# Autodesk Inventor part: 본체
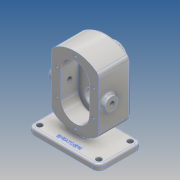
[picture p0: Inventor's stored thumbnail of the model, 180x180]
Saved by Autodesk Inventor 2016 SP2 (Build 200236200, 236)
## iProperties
Created: 2019-03
Part Number: 본체
Material: 알루미늄 6061
Document SubType Name: Modeling
Designer: EZ
Density: 2.7 g/cm^3
Appearance: 알루미늄 - 평지
Mass: 1187.19 g
Surface Area: 719.604 cm^2
Volume: 439.7 cm^3
Author: EZ
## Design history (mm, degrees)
sketch "스케치1"
  geometry: L1 (60, -36.5)-(-60, -36.5); L2 (-60, -36.5)-(-60, 36.5); L3 (-60, 36.5)-(60, 36.5); L4 (60, 36.5)-(60, -36.5); L5 (60, -36.5)-(-60, 36.5); L6 (-60, -36.5)-(60, 36.5); 1 further point
  constraints: 12 end point, 2 midpoint, 2 parallel, 1 horizontal, 1 perpendicular
  dimensions: "d0" = 120 distance of L2.end L3.end; "d1" = 73 distance of L1.end L2.end
extrude "돌출1" new body sketch "스케치1" distance "d2" = 10; taper "d3" = 0 deg
fillet "모깎기1" dims "d4" = 10
sketch "스케치2"
  geometry: L1 (-50, 36.5)-(50, 36.5) reference; L2 (60, 26.5)-(60, -26.5) reference; L3 (50, -36.5)-(-50, -36.5) reference; L4 (-60, -26.5)-(-60, 26.5) reference; A1 r 10 centre (-50, 26.5) between (-50, 36.5) and (-60, 26.5) reference; A2 r 10 centre (50, 26.5) between (60, 26.5) and (50, 36.5) reference; A3 r 10 centre (50, -26.5) between (50, -36.5) and (60, -26.5) reference; A4 r 10 centre (-50, -26.5) between (-60, -26.5) and (-50, -36.5) reference; 5 further points
  constraints: 4 coincident
hole "구멍1" sketch "스케치2" at (-50, 26.5), (-50, -26.5), (50, -26.5), (50, 26.5) diameter "d5" = 9; stored, may be unused: countersink angle "d9" = 90 deg, drill point angle "d11" = 118 deg; dims "d6" = 6, "d7" = 4, "d8" = 2, "d10" = 8
sketch "스케치3"
  geometry: L1 (36.5, 0)-(-36.5, 0) reference; L2 (-36.5, 0)-(-36.5, 10) reference; L3 (-36.5, 10)-(36.5, 10) reference; L4 (36.5, 10)-(36.5, 0) reference; L5 (-16.5, 78)-(36.5, 78); L6 (-16.5, 78)-(-16.5, 138); L7 (-16.5, 138)-(36.5, 138); L8 (36.5, 138)-(36.5, 78)
  constraints: 8 end point, 3 perpendicular, 1 horizontal
  dimensions: "d13" = 78 distance between parallel lines of L5 L1; "d14" = 138 distance between parallel lines of L1 L7; "d15" = 53 distance between parallel lines of L4 L6; "d16" = 53 distance between parallel lines of L6 L8
extrude "돌출2" join sketch "스케치3" stored distance "d18" = 80; taper "d19" = 0 deg
sketch "스케치4"
  geometry: L1 (80, 0)-(80, -120) reference; L2 (0, 0)-(80, 0) reference; L3 (0, 0)-(0, -120) reference; L4 (0, -120)-(80, -120) reference; A1 r 60 centre (40, -60) between (0, -104.721) and (80, -104.721); A2 r 60 centre (40, -60) between (80, -15.279) and (0, -15.279); A3 r 60 centre (40, -60) between (80, -104.721) and (80, -15.279); 2 further points
  constraints: 6 point on circle, 4 point on line, 3 centre point, 2 tangent, 1 midpoint, 1 vertical alignment
  dimensions: "d20" = 120 diameter of A1
extrude "돌출3" cut sketch "스케치4" distance "d21" = 80; taper "d22" = 0 deg
sketch "스케치5"
  geometry: L1 (-50, 36.5)-(50, 36.5) reference; L2 (60, 26.5)-(60, -26.5) reference; L3 (50, -36.5)-(-50, -36.5) reference; L4 (-60, -26.5)-(-60, 26.5) reference; L5 (0, 36.5)-(0, -36.5); L6 (-6, 36.5)-(-6, -6.5); L7 (-6, -6.5)-(6, -6.5); L8 (6, -6.5)-(6, 36.5); C1 r 4.5 at (50, -26.5) reference; C2 r 4.5 at (-50, 26.5) reference; C3 r 4.5 at (-50, -26.5) reference; C4 r 4.5 at (50, 26.5) reference; A1 r 10 centre (-50, 26.5) between (-50, 36.5) and (-60, 26.5) reference; A2 r 10 centre (50, 26.5) between (60, 26.5) and (50, 36.5) reference; A3 r 10 centre (50, -26.5) between (50, -36.5) and (60, -26.5) reference; A4 r 10 centre (-50, -26.5) between (-60, -26.5) and (-50, -36.5) reference
  constraints: 8 end point, 2 midpoint, 2 perpendicular, 2 point on line, 1 vertical
  dimensions: "d27" = 43 distance of L6.start L6.end; "d28" = 6 distance between parallel lines of L5 L6; "d29" = 12 distance between parallel lines of L6 L8
extrude "돌출4" join sketch "스케치5" stored distance "d30" = 80; taper "d31" = 0 deg
sketch "스케치6"
  geometry: L1 (40, 44.721)-(40, -44.721) reference; L2 (-40, 44.721)-(-40, -44.721) reference; L3 (0, 22)-(0, -22); L4 (24, 22)-(24, -22); L5 (-24, -22)-(-24, 22); A1 r 60 centre (0, 0) between (-40, -44.721) and (40, -44.721) reference; A2 r 60 centre (0, 0) between (40, 44.721) and (-40, 44.721) reference; A3 r 24 centre (0, 22) between (24, 22) and (-24, 22); A4 r 24 centre (0, -22) between (-24, -22) and (24, -22); 2 further points
  constraints: 8 end point, 4 point on circle, 4 tangent, 2 centre point, 1 midpoint, 1 parallel, 1 vertical
  dimensions: "d32" = 78 distance of point (0, -78) point (0, 0); "d34" = 22 distance of A1.centre L3.start; "d35" = 44 distance of L3.end L3.start; "d39" = 24 radius of A3
extrude "돌출5" cut sketch "스케치6" distance "d40" = 29; taper "d41" = 0 deg
sketch "스케치7"
  geometry: L1 (24, 22)-(24, -22) reference; L2 (-24, -22)-(-24, 22) reference; L3 (40, 44.721)-(40, -44.721) reference; L4 (-40, 44.721)-(-40, -44.721) reference; L5 (0, 22)-(0, -22); L6 (31, 22)-(31, -22); L7 (-31, -22)-(-31, 22); A1 r 24 centre (0, 22) between (24, 22) and (-24, 22) reference; A2 r 24 centre (0, -22) between (-24, -22) and (24, -22) reference; A3 r 60 centre (0, 0) between (-40, -44.721) and (40, -44.721) reference; A4 r 60 centre (0, 0) between (40, 44.721) and (-40, 44.721) reference; A5 r 31 centre (0, 22) between (31, 22) and (-31, 22); A6 r 31 centre (0, -22) between (-31, -22) and (31, -22); 8 further points
  constraints: 8 end point, 6 point on circle, 4 coincident, 4 tangent, 2 centre point, 1 midpoint, 1 parallel, 1 vertical
  dimensions: "d42" = 31 radius of A5
hole "구멍2" sketch "스케치7" at (0, 53), (-31, 22), (31, 22), (31, -22), (-31, -22), (0, -53) diameter "d43" = 4.134; stored, may be unused: countersink angle "d47" = 90 deg, drill point angle "d49" = 118 deg; dims "d44" = 10, "d45" = 4, "d46" = 2, "d48" = 12
sketch "스케치8"
  geometry: L1 (-33.279, 36.5)-(-33.279, -16.5) reference; L2 (-122.721, -16.5)-(-33.279, -16.5) reference; L3 (-122.721, -16.5)-(-122.721, 36.5) reference; L4 (-122.721, 36.5)-(-33.279, 36.5) reference; L5 (0, -26.5)-(0, 26.5) reference; C1 r 11 at (-78, -2.5); 1 further point
  constraints: 1 centre point
  dimensions: "d51" = 22 diameter of C1; "d52" = 78 distance from line of L5 C1.centre; "d53" = 14 distance from line of L2 C1.centre
extrude "돌출6" join sketch "스케치8" distance "d54" = 8; taper "d55" = 0 deg
hole "구멍3" diameter "d59" = 8.376; stored, may be unused: countersink angle "d63" = 90 deg, drill point angle "d65" = 118 deg; dims "d60" = 20, "d61" = 4, "d62" = 2, "d64" = 27.3, "d103" = 10, "d104" = 10
fillet "모깎기4" dims "d66" = 3
sketch "스케치10"
  geometry: L1 (-40, -44.721)-(-40, 44.721) reference; L2 (40, 44.721)-(40, -44.721) reference; L3 (6, -62.354)-(6, -65) reference; L4 (9, -68)-(60, -68) reference; L5 (60, -68)-(60, -78) reference; L6 (60, -78)-(-60, -78) reference; L7 (-60, -78)-(-60, -68) reference; L8 (-60, -68)-(-9, -68) reference; L9 (-6, -65)-(-6, -62.354) reference; L10 (-24, 22)-(-24, -22) reference; L11 (24, -22)-(24, 22) reference; C1 r 12.5 at (0, -22); A1 r 3 centre (-9, -62.354) between (-6, -62.354) and (-8.571, -59.385) reference; A2 r 60 centre (0, 0) between (-40, -44.721) and (-8.571, -59.385) reference; A3 r 60 centre (0, 0) between (40, 44.721) and (-40, 44.721) reference; A4 r 60 centre (0, 0) between (8.571, -59.385) and (40, -44.721) reference; A5 r 3 centre (9, -62.354) between (8.571, -59.385) and (6, -62.354) reference; A6 r 3 centre (9, -65) between (6, -65) and (9, -68) reference; A7 r 3 centre (-9, -65) between (-9, -68) and (-6, -65) reference; A8 r 24 centre (0, 22) between (24, 22) and (-24, 22) reference; A9 r 24 centre (0, -22) between (-24, -22) and (24, -22) reference; 1 further point
  constraints: 1 centre point, 1 coincident
  dimensions: "d72" = 25 diameter of C1
extrude "돌출7" cut sketch "스케치10" distance "d73" = 15; taper "d74" = 0 deg
sketch "스케치11"
  geometry: L1 (36.5, 122.721)-(36.5, 33.279) reference; L2 (36.5, 119)-(53.5, 119); L3 (53.5, 100)-(36.5, 100); L4 (-16.5, 56)-(-16.5, 100) reference; L5 (-16.5, 78)-(36.5, 78); L6 (-26.5, 0)-(26.5, 0) reference; L7 (53.5, 119)-(53.5, 100); 2 further points
  constraints: 8 end point, 2 horizontal, 2 midpoint, 2 point on line, 1 perpendicular, 1 vertical
  dimensions: "d76" = 78 distance between parallel lines of L6 L5; "d77" = 22 distance between parallel lines of L5 L3; "d79" = 17 distance of L2.start L2.end; "d80" = 38 diameter of L2 L3
revolve "회전1" sketch "스케치11" stored, may be unused: angle "d81" = 90 deg
fillet "모깎기6" dims "d82" = 3
sketch "스케치12"
  geometry: L1 (-16.5, 32)-(12.5, 32) reference; L2 (12.5, 32)-(12.5, 43.5) reference; L3 (12.5, 43.5)-(27.5, 43.5) reference; L4 (27.5, 43.5)-(27.5, 68.5) reference; L5 (27.5, 68.5)-(12.5, 68.5) reference; L6 (12.5, 68.5)-(12.5, 124) reference; L7 (12.5, 124)-(-16.5, 124) reference; L8 (-16.5, 124)-(-16.5, 128.933) reference; L9 (-16.5, 128.933)-(-4.5, 128.933) reference; L10 (-4.5, 128.933)-(-3.258, 131) reference; L11 (-3.258, 131)-(-4.5, 133.067) reference; L12 (-4.5, 133.067)-(-16.5, 133.067) reference; L13 (-16.5, 133.067)-(-16.5, 138) reference; L14 (-16.5, 138)-(36.5, 138) reference; L15 (36.5, 138)-(36.5, 122) reference; L16 (39.5, 119)-(53.5, 119) reference; L17 (53.5, 119)-(53.5, 81) reference; L18 (53.5, 81)-(39.5, 81) reference; L19 (36.5, 78)-(36.5, 0) reference; L20 (36.5, 0)-(-36.5, 0) reference; L21 (-36.5, 0)-(-36.5, 10) reference; L22 (-36.5, 10)-(-6.5, 10) reference; L23 (-6.5, 10)-(-6.5, 18) reference; L24 (-6.5, 18)-(-16.5, 18) reference; L25 (-16.5, 18)-(-16.5, 22.933) reference; L26 (-16.5, 22.933)-(-4.5, 22.933) reference; L27 (-4.5, 22.933)-(-3.258, 25) reference; L28 (-3.258, 25)-(-4.5, 27.067) reference; L29 (-4.5, 27.067)-(-16.5, 27.067) reference; L30 (-16.5, 27.067)-(-16.5, 32) reference; L31 (12.5, 78)-(36.5, 78); L32 (12.5, 100)-(53.5, 100); L33 (12.5, 112.5)-(27.5, 112.5); L34 (27.5, 112.5)-(27.5, 108.5); L35 (27.5, 108.5)-(46.2, 108.5); L36 (46.2, 108.5)-(46.2, 113.7); L37 (46.5, 114)-(53.5, 114); L38 (12.5, 112.5)-(12.5, 100); L39 (53.5, 114)-(53.5, 100); A1 r 3 centre (39.5, 122) between (36.5, 122) and (39.5, 119) reference; A2 r 3 centre (39.5, 78) between (39.5, 81) and (36.5, 78) reference; A3 r 0.3 centre (46.5, 113.7) between (46.5, 114) and (46.2, 113.7); 2 further points
  constraints: 18 end point, 7 point on line, 4 perpendicular, 2 collinear, 2 horizontal, 2 point on circle, 2 tangent, 1 centre point, 1 midpoint, 1 vertical
  dimensions: "d83" = 78 distance between parallel lines of L20 L31; "d84" = 22 distance between parallel lines of L31 L32; "d85" = 7.3 distance of point (46.2, 114) L37.end; "d86" = 15 distance of L33.start L33.end; "d87" = 25 diameter of L33 L32; "d88" = 17 diameter of L35 L32; "d89" = 28 diameter of L37 L32; "d90" = 0.3 radius of A3
revolve "회전2" sketch "스케치12" stored, may be unused: angle "d91" = 90 deg
fillet "모깎기7" dims "d92" = 3
fillet "모깎기8" dims "d93" = 3
fillet "모깎기9" dims "d94" = 3
fillet "모깎기10" dims "d95" = 10
chamfer "모따기1" distance "d96" = 1; stored, may be unused: second distance "d97" = 2, angle "d98" = 30 deg
sketch "스케치13"
  geometry: L1 (-50, -36.5)-(50, -36.5) reference; L2 (-60, 26.5)-(-60, -26.5) reference; 2 further points
  constraints: 1 other
  dimensions: "d99" = 10 distance from line of point (0, -26.5) L1; "d100" = 60 distance from line of L2 point (0, -26.5)
feature "엠보싱1" sketch "스케치13" dims "d0" = 120, "d1" = 73, "d101" = 0.5, "d102" = 0
chamfer "모따기2" distance "d105" = 0.7; stored, may be unused: second distance "d106" = 2, angle "d107" = 30 deg
node "솔리드1"
mirror "대칭1"
mirror "대칭2"
node "투영된 루프1"
node "투영된 루프2"
node "투영된 루프3"
node "투영된 루프4"
node "투영된 루프5"
node "투영된 루프6"
node "절단 모서리 투영1"
node "절단 모서리 투영3"
node "절단 모서리 투영4"
